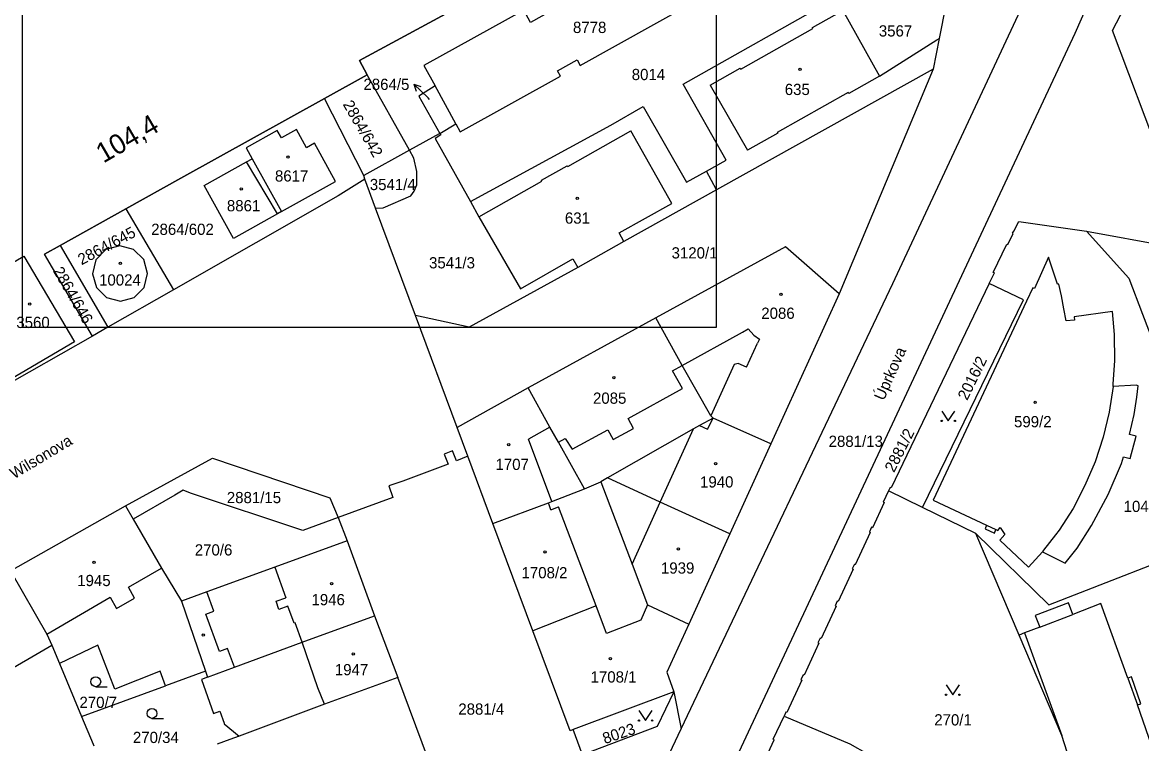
# Model space of a CAD drawing. Extents: x -564952 to -564307, y -1202373 to -1201847.
# Drawn here: x -564645.4 to -564475.9, y -1202200.5 to -1202091.3 of the extents above; entities that cross this region are included whole.
import ezdxf

# ---------------------------------------------------------------- set-up
doc = ezdxf.new("R2010")
doc.units = 0
for name, color, linetype in [('Hranice parcel', 7, 'Continuous'), ('Parcelní čísla', 7, 'Continuous'), ('Pop  PČ popisy', 7, 'Continuous'), ('Vnitřní kresba', 7, 'Continuous'), ('Vrstva 63', 7, 'Continuous'), ('Vrstva 7', 7, 'Continuous'), ('Značky budov', 7, 'Continuous'), ('Značky kultur', 7, 'Continuous')]:
    doc.layers.add(name, color=color, linetype=linetype)

msp = doc.modelspace()

# ---------------------------------------------------------------- linework, layer by layer
at = {"layer": 'Hranice parcel'}
for p, q in [((-564545.32, -1202100.65), (-564521.82, -1202087.35)), ((-564506.54, -1202093.7), (-564507.46, -1202098.37)), ((-564584.58, -1202097.8), (-564582.88, -1202100.89)), ((-564507.46, -1202098.37), (-564540.26, -1202116.64)), ((-564507.46, -1202098.37), (-564521.72, -1202132.36)), ((-564599.65, -1202102.83), (-564593.15, -1202099.21)), ((-564586.77, -1202110.65), (-564593.15, -1202099.21)), ((-564579.72, -1202106.62), (-564582.88, -1202100.89)), ((-564593.69, -1202114.49), (-564599.65, -1202102.83)), ((-564582.16, -1202108.09), (-564579.72, -1202106.62)), ((-564577.51, -1202118.41), (-564556.26, -1202106.85)), ((-564610.56, -1202111.95), (-564606.12, -1202119.94)), ((-564586.77, -1202110.65), (-564593.69, -1202114.49)), ((-564540.26, -1202116.64), (-564541.8, -1202113.81)), ((-564593.53, -1202115), (-564593.69, -1202114.49)), ((-564591.89, -1202119.4), (-564593.53, -1202115)), ((-564577.51, -1202118.41), (-564576.24, -1202120.72)), ((-564639.63, -1202125.04), (-564629.71, -1202119.53)), ((-564629.71, -1202119.53), (-564622.49, -1202131.77)), ((-564585.83, -1202135.64), (-564591.89, -1202119.4)), ((-564484.26, -1202122.87), (-564466.68, -1202126.15)), ((-564642, -1202126.36), (-564639.63, -1202125.04)), ((-564639.63, -1202125.04), (-564632.41, -1202137.43)), ((-564634.78, -1202138.78), (-564642, -1202126.36)), ((-564545.63, -1202198.24), (-564513.56, -1202130.84)), ((-564622.49, -1202131.77), (-564632.41, -1202137.43)), ((-564521.72, -1202132.36), (-564532.03, -1202155.1)), ((-564579.54, -1202152.6), (-564585.83, -1202135.64)), ((-564632.41, -1202137.43), (-564634.78, -1202138.78)), ((-564549.46, -1202136.04), (-564568.78, -1202146.64)), ((-564634.78, -1202138.78), (-564652.84, -1202149.09)), ((-564568.78, -1202146.64), (-564579.54, -1202152.6)), ((-564532.03, -1202155.1), (-564540.8, -1202151.2)), ((-564577.92, -1202156.95), (-564579.54, -1202152.6)), ((-564532.03, -1202155.1), (-564538.25, -1202168.75)), ((-564574.13, -1202167.15), (-564577.92, -1202156.95)), ((-564560.27, -1202161.89), (-564557.78, -1202160.84)), ((-564556.78, -1202160.27), (-564557.78, -1202160.84)), ((-564513.99, -1202161.71), (-564514.25, -1202162.22)), ((-564509.08, -1202164.74), (-564514.25, -1202162.22)), ((-564647.18, -1202174.34), (-564629.78, -1202164.5)), ((-564629.78, -1202164.5), (-564628.62, -1202166.49)), ((-564500.99, -1202168.69), (-564509.08, -1202164.74)), ((-564597.56, -1202166.27), (-564596.22, -1202169.81)), ((-564568.07, -1202183.42), (-564574.13, -1202167.15)), ((-564596.22, -1202169.81), (-564607.17, -1202173.79)), ((-564596.22, -1202169.81), (-564592.04, -1202181.12)), ((-564538.25, -1202168.75), (-564544.47, -1202182.4)), ((-564494.46, -1202184.06), (-564500.99, -1202168.69)), ((-564621.26, -1202178.92), (-564617.66, -1202189.51)), ((-564550.71, -1202179.48), (-564544.47, -1202182.4)), ((-564602.99, -1202185.12), (-564592.04, -1202181.12)), ((-564592.04, -1202181.12), (-564588.53, -1202190.48)), ((-564488, -1202199.27), (-564494.46, -1202184.06)), ((-564633.95, -1202185.59), (-564639.75, -1202188.35)), ((-564639.75, -1202188.35), (-564636.4, -1202196.4)), ((-564617.66, -1202189.51), (-564623.69, -1202191.73)), ((-564617.66, -1202189.51), (-564617.35, -1202190.41)), ((-564636.4, -1202196.4), (-564623.69, -1202191.73)), ((-564546.74, -1202192.63), (-564562, -1202198.37)), ((-564546.74, -1202192.63), (-564545.63, -1202198.24)), ((-564547.82, -1202202.85), (-564545.63, -1202198.24)), ((-564481.73, -1202218.41), (-564488, -1202199.27))]:
    msp.add_line(p, q, dxfattribs=at)
for points in [[(-564490.61, -1202037.43), (-564485.84, -1202045.71), (-564483.2, -1202051.32), (-564481.59, -1202056.49), (-564480.56, -1202063.21), (-564480.33, -1202068.72), (-564480.73, -1202075.46), (-564482.21, -1202082.88), (-564484.11, -1202088.61), (-564486.01, -1202092.94), (-564492.26, -1202106.34), (-564537.63, -1202203.39), (-564539.05, -1202206.7), (-564540.49, -1202210.49), (-564542.11, -1202215.98)], [(-564501.71, -1202041.71), (-564510.03, -1202046.63), (-564524.57, -1202055.16), (-564524.06, -1202056.17), (-564524.06, -1202056.17), (-564558.26, -1202076.16), (-564568.86, -1202083.22), (-564594.31, -1202097.06), (-564593.15, -1202099.21), (-564599.65, -1202102.83), (-564621.36, -1202114.89), (-564629.71, -1202119.53), (-564639.63, -1202125.04), (-564642, -1202126.36)], [(-564513.56, -1202130.84), (-564493.88, -1202088.69), (-564491.84, -1202083.54), (-564490.32, -1202078.4), (-564489.39, -1202070.74), (-564489.54, -1202063.63), (-564490.98, -1202056.1), (-564493.78, -1202048.14), (-564495.85, -1202043.53)], [(-564593.15, -1202099.21), (-564594.31, -1202097.06), (-564568.86, -1202083.22), (-564558.26, -1202076.16)], [(-564503.26, -1202076.98), (-564506.29, -1202092.45), (-564506.54, -1202093.7)], [(-564471.12, -1202112.99), (-564472.91, -1202112.19), (-564480.33, -1202092.49), (-564473.1, -1202078.61)], [(-564579.72, -1202106.62), (-564579.07, -1202107.87), (-564563.9, -1202099.44), (-564564.37, -1202098.6), (-564561.39, -1202096.95), (-564560.92, -1202097.79), (-564538.6, -1202085.32), (-564537.9, -1202086.54), (-564536.02, -1202085.5), (-564536.68, -1202084.26), (-564534.85, -1202083.23)], [(-564566.49, -1202087.78), (-564565.45, -1202089.65), (-564568.43, -1202091.3), (-564569.47, -1202089.44), (-564584.58, -1202097.8)], [(-564520.73, -1202089.2), (-564521.15, -1202089.48), (-564515.62, -1202099.42)], [(-564515.62, -1202099.42), (-564506.92, -1202093.94), (-564506.54, -1202093.7)], [(-564582.88, -1202100.89), (-564585.37, -1202102.47), (-564582.16, -1202108.09)], [(-564541.8, -1202113.81), (-564538.8, -1202112.13), (-564545.32, -1202100.65)], [(-564629.71, -1202119.53), (-564621.36, -1202114.89), (-564599.65, -1202102.83)], [(-564556.26, -1202106.85), (-564551.4, -1202104.02), (-564544.83, -1202115.5), (-564541.8, -1202113.81)], [(-564606.12, -1202119.94), (-564597.95, -1202115.39), (-564601.16, -1202109.59), (-564602.38, -1202110.27), (-564603.88, -1202107.5), (-564606.16, -1202108.76), (-564606.78, -1202107.65), (-564611.49, -1202110.28), (-564610.56, -1202111.95)], [(-564582.16, -1202108.09), (-564582.25, -1202108.14), (-564586.77, -1202110.65)], [(-564582.16, -1202108.09), (-564582.03, -1202108.32), (-564582.87, -1202108.86), (-564577.51, -1202118.41)], [(-564606.12, -1202119.94), (-564606.73, -1202120.28), (-564613.43, -1202124), (-564617.83, -1202116), (-564611.43, -1202112.4), (-564610.56, -1202111.95)], [(-564591.89, -1202119.4), (-564590.74, -1202119.38), (-564586.58, -1202117.56), (-564586.07, -1202116.85), (-564585.67, -1202115.88), (-564585.64, -1202113.86), (-564586.1, -1202111.83), (-564586.77, -1202110.65)], [(-564593.53, -1202115), (-564597.56, -1202117.54), (-564622.49, -1202131.77)], [(-564540.26, -1202116.64), (-564554.31, -1202124.46), (-564561.29, -1202128.42)], [(-564576.24, -1202120.72), (-564569.95, -1202131.64), (-564562.02, -1202127.1), (-564561.29, -1202128.42)], [(-564495.28, -1202122.88), (-564494.48, -1202121.45), (-564484.26, -1202122.87)], [(-564498.98, -1202130.82), (-564498.2, -1202129.22), (-564498.38, -1202129.13), (-564496.32, -1202124.84), (-564496.15, -1202124.92), (-564495.36, -1202123.27), (-564495.45, -1202123.22), (-564495.28, -1202122.88)], [(-564484.26, -1202122.87), (-564477.85, -1202129.99), (-564475.76, -1202135.44), (-564470.96, -1202147.96)], [(-564634.23, -1202127.23), (-564634.77, -1202129.33), (-564634.17, -1202131.42), (-564632.66, -1202132.95), (-564630.54, -1202133.5), (-564628.45, -1202132.93), (-564626.94, -1202131.4), (-564626.41, -1202129.29), (-564626.99, -1202127.19), (-564628.53, -1202125.67), (-564630.63, -1202125.11), (-564632.72, -1202125.68), (-564634.23, -1202127.23)], [(-564521.72, -1202132.36), (-564529.81, -1202125.26), (-564549.46, -1202136.04)], [(-564649.66, -1202146.78), (-564652.32, -1202142.22), (-564654.66, -1202138.21), (-564657.3, -1202133.69), (-564645.16, -1202126.66), (-564637.48, -1202139.67), (-564649.66, -1202146.78)], [(-564483.51, -1202167.45), (-564480.96, -1202162.75), (-564478.98, -1202158.08), (-564478.64, -1202157.07), (-564477.65, -1202157.31), (-564476.75, -1202153.95), (-564477.75, -1202153.68), (-564477.04, -1202150.63), (-564476.65, -1202148.03), (-564476.45, -1202146.29), (-564476.74, -1202146.23), (-564480.24, -1202146.43), (-564480.21, -1202145.99), (-564479.97, -1202142.53), (-564480.01, -1202138.56), (-564480.32, -1202135.08), (-564486.13, -1202135.85), (-564486.06, -1202136.35), (-564487.36, -1202136.45), (-564487.67, -1202134.63), (-564488.03, -1202132.71), (-564488.44, -1202130.91), (-564488.66, -1202130.93), (-564489.99, -1202126.85), (-564492.12, -1202131.58), (-564492.39, -1202131.47), (-564493.34, -1202133.51), (-564507.46, -1202163.65), (-564499.39, -1202167.41), (-564499.61, -1202167.95), (-564498.2, -1202168.6), (-564497.98, -1202168.07), (-564497.67, -1202168.21), (-564497.31, -1202167.78), (-564496.62, -1202168.83), (-564497.38, -1202169.7), (-564493.03, -1202173.79), (-564490.94, -1202171.44), (-564487.48, -1202173.17), (-564485.69, -1202170.87), (-564483.51, -1202167.45)], [(-564561.29, -1202128.42), (-564577.72, -1202137.44), (-564585.83, -1202135.64)], [(-564498.98, -1202130.82), (-564513.85, -1202161.77), (-564513.99, -1202161.71)], [(-564509.08, -1202164.74), (-564493.77, -1202133.3), (-564498.98, -1202130.82)], [(-564540.8, -1202151.2), (-564541.14, -1202150.85), (-564545.46, -1202143.23), (-564549.46, -1202136.04)], [(-564560.27, -1202161.89), (-564564.19, -1202154.86), (-564565.51, -1202152.55), (-564568.78, -1202146.64)], [(-564540.8, -1202151.2), (-564542.86, -1202152.33), (-564543.76, -1202152.82), (-564556.78, -1202160.27)], [(-564577.92, -1202156.95), (-564579.66, -1202157.65), (-564580.24, -1202156.18), (-564581.49, -1202156.65), (-564580.9, -1202158.2), (-564587.76, -1202160.75), (-564589.91, -1202161.48), (-564589.27, -1202163.23), (-564597.56, -1202166.27)], [(-564629.78, -1202164.5), (-564616.6, -1202157.29), (-564598.81, -1202163.26), (-564597.56, -1202166.27)], [(-564557.78, -1202160.84), (-564553.06, -1202173.32), (-564550.71, -1202179.48)], [(-564538.25, -1202168.75), (-564548.8, -1202163.92), (-564556.78, -1202160.27)], [(-564597.56, -1202166.27), (-564602.89, -1202168.22), (-564619.91, -1202162.56), (-564621.02, -1202162.13), (-564622.28, -1202162.87), (-564628.62, -1202166.49)], [(-564574.13, -1202167.15), (-564565.71, -1202164.02), (-564565.23, -1202163.83), (-564560.27, -1202161.89)], [(-564514.25, -1202162.22), (-564515.03, -1202163.91), (-564514.9, -1202163.97), (-564516.67, -1202167.81), (-564516.81, -1202167.74)], [(-564628.62, -1202166.49), (-564624.3, -1202173.94), (-564621.26, -1202178.92)], [(-564516.81, -1202167.74), (-564517.13, -1202168.44), (-564517, -1202168.51), (-564519.26, -1202173.4), (-564519.4, -1202173.33), (-564519.73, -1202174.04), (-564519.59, -1202174.1), (-564521.85, -1202178.98), (-564521.99, -1202178.92), (-564522.32, -1202179.64), (-564522.18, -1202179.7), (-564524.44, -1202184.58), (-564524.58, -1202184.52), (-564524.91, -1202185.23)], [(-564500.99, -1202168.69), (-564489.98, -1202179.46), (-564465.07, -1202169.78)], [(-564647.18, -1202174.34), (-564641.67, -1202183.91), (-564640.9, -1202185.58), (-564639.75, -1202188.35)], [(-564607.17, -1202173.79), (-564617.45, -1202177.53), (-564621.26, -1202178.92)], [(-564556.93, -1202183.82), (-564558.51, -1202179.64), (-564568.07, -1202183.42)], [(-564550.71, -1202179.48), (-564551.74, -1202181.8), (-564556.93, -1202183.82)], [(-564458.87, -1202196.74), (-564473.97, -1202202.06), (-564476.51, -1202194.63), (-564476.01, -1202194.45), (-564477.42, -1202190.36), (-564477.98, -1202190.57), (-564482.07, -1202179.28), (-564486.31, -1202180.92), (-564486.99, -1202179.15), (-564492.02, -1202181.09), (-564491.34, -1202182.86), (-564493.63, -1202183.74), (-564494.46, -1202184.06)], [(-564544.47, -1202182.4), (-564547.79, -1202189.69), (-564546.74, -1202192.63)], [(-564562, -1202198.37), (-564562.44, -1202198.54), (-564568.07, -1202183.42)], [(-564623.69, -1202191.73), (-564624.53, -1202189.5), (-564631.36, -1202192.25), (-564633.95, -1202185.59)], [(-564617.35, -1202190.41), (-564613.26, -1202188.9), (-564602.99, -1202185.12)], [(-564524.91, -1202185.23), (-564524.77, -1202185.29), (-564527.02, -1202190.14)], [(-564527.02, -1202190.14), (-564527.16, -1202190.08), (-564527.51, -1202190.83), (-564527.37, -1202190.89), (-564529.64, -1202195.79), (-564529.77, -1202195.73), (-564530.05, -1202196.32)], [(-564617.35, -1202190.41), (-564618.26, -1202190.8), (-564616.42, -1202195.93), (-564615.48, -1202195.6), (-564614.84, -1202197.38), (-564614.8, -1202197.48), (-564612.57, -1202199.34)], [(-564588.53, -1202190.48), (-564599.64, -1202194.53), (-564612.57, -1202199.34)], [(-564573.02, -1202232.4), (-564578.7, -1202216.81), (-564583.08, -1202205.12), (-564588.53, -1202190.48)], [(-564546.74, -1202192.63), (-564549.25, -1202197.89), (-564560.56, -1202202.2), (-564562, -1202198.37)], [(-564636.4, -1202196.4), (-564634.68, -1202200.55), (-564634.56, -1202200.83)], [(-564531.54, -1202199.9), (-564531.68, -1202199.84), (-564530.05, -1202196.32)], [(-564530.05, -1202196.32), (-564520.07, -1202200.53), (-564517.42, -1202202.04), (-564516.45, -1202203.06), (-564515.15, -1202205.05), (-564512.46, -1202207.51), (-564511.71, -1202209.04), (-564510.44, -1202211.22), (-564507.27, -1202214.23), (-564507.22, -1202214.4), (-564507.04, -1202214.34), (-564506.39, -1202216.27), (-564506.24, -1202216.69), (-564503.5, -1202224.55), (-564503.06, -1202225.8)], [(-564612.57, -1202199.34), (-564613.95, -1202199.85), (-564615.87, -1202200.58)], [(-564534.37, -1202205.65), (-564534.23, -1202205.71), (-564531.54, -1202199.9)]]:
    msp.add_lwpolyline(points, dxfattribs=at)
at = {"layer": 'Pop  PČ popisy'}
for p, q in [((-564583.95, -1202102.73), (-564586.11, -1202100.65)), ((-564586.11, -1202100.65), (-564585.04, -1202100.98)), ((-564586.11, -1202100.65), (-564585.74, -1202101.7)), ((-564583.72, -1202102.95), (-564583.95, -1202102.73))]:
    msp.add_line(p, q, dxfattribs=at)
at = {"layer": 'Vnitřní kresba'}
for p, q in [((-564525.76, -1202092.07), (-564521.15, -1202089.48)), ((-564536.61, -1202098.36), (-564525.68, -1202092.21)), ((-564525.68, -1202092.21), (-564525.76, -1202092.07)), ((-564541.22, -1202100.77), (-564536.69, -1202098.22)), ((-564536.69, -1202098.22), (-564536.61, -1202098.36)), ((-564515.62, -1202099.42), (-564520.26, -1202102.03)), ((-564541.22, -1202100.77), (-564535.57, -1202110.64)), ((-564520.34, -1202101.89), (-564531.07, -1202107.93)), ((-564520.26, -1202102.03), (-564520.34, -1202101.89)), ((-564562.81, -1202113.12), (-564553.23, -1202107.7)), ((-564547.06, -1202118.68), (-564553.23, -1202107.7)), ((-564530.99, -1202108.06), (-564535.57, -1202110.64)), ((-564531.07, -1202107.93), (-564530.99, -1202108.06)), ((-564606.73, -1202120.28), (-564611.43, -1202112.4)), ((-564566.79, -1202115.19), (-564562.89, -1202112.98)), ((-564562.89, -1202112.98), (-564562.81, -1202113.12)), ((-564576.24, -1202120.72), (-564566.72, -1202115.33)), ((-564566.72, -1202115.33), (-564566.79, -1202115.19)), ((-564555.03, -1202123.14), (-564547.06, -1202118.68)), ((-564554.31, -1202124.46), (-564555.03, -1202123.14)), ((-564545.46, -1202143.23), (-564536.36, -1202138.2)), ((-564536.36, -1202138.2), (-564535.46, -1202137.7)), ((-564535.46, -1202137.7), (-564534.65, -1202138.66)), ((-564534.65, -1202138.66), (-564533.78, -1202139.23)), ((-564533.78, -1202139.23), (-564534.07, -1202139.86)), ((-564535.72, -1202143.49), (-564534.07, -1202139.86)), ((-564546.94, -1202144.04), (-564545.46, -1202143.23)), ((-564545.45, -1202146.73), (-564546.94, -1202144.04)), ((-564537.62, -1202143.09), (-564541.14, -1202150.85)), ((-564537.02, -1202142.91), (-564537.62, -1202143.09)), ((-564535.72, -1202143.49), (-564537.02, -1202142.91)), ((-564553.65, -1202151.27), (-564545.45, -1202146.73)), ((-564480.24, -1202146.43), (-564480.83, -1202150.3)), ((-564541.64, -1202152.88), (-564540.8, -1202151.2)), ((-564480.83, -1202150.3), (-564481.74, -1202154.11)), ((-564565.51, -1202152.55), (-564568.72, -1202154.4)), ((-564555.93, -1202154.46), (-564552.84, -1202152.77)), ((-564552.84, -1202152.77), (-564553.65, -1202151.27)), ((-564548.8, -1202163.92), (-564543.76, -1202152.82)), ((-564542.86, -1202152.33), (-564541.64, -1202152.88)), ((-564565.23, -1202163.83), (-564568.72, -1202154.4)), ((-564564.19, -1202154.86), (-564563.17, -1202154.29)), ((-564563.17, -1202154.29), (-564562.13, -1202155.89)), ((-564562.13, -1202155.89), (-564556.75, -1202152.96)), ((-564556.75, -1202152.96), (-564555.93, -1202154.46)), ((-564481.74, -1202154.11), (-564482.96, -1202157.83)), ((-564482.96, -1202157.83), (-564484.49, -1202161.42)), ((-564484.49, -1202161.42), (-564486.29, -1202164.9)), ((-564565.35, -1202165.08), (-564565.71, -1202164.02)), ((-564565.35, -1202165.08), (-564564.19, -1202164.63)), ((-564558.51, -1202179.64), (-564564.19, -1202164.63)), ((-564553.06, -1202173.32), (-564548.8, -1202163.92)), ((-564486.29, -1202164.9), (-564488.41, -1202168.17)), ((-564499.39, -1202167.41), (-564497.98, -1202168.07)), ((-564488.95, -1202168.87), (-564490.77, -1202171.21)), ((-564488.41, -1202168.17), (-564488.95, -1202168.87)), ((-564490.77, -1202171.21), (-564490.94, -1202171.44)), ((-564629.29, -1202176.8), (-564624.3, -1202173.94)), ((-564607.17, -1202173.79), (-564605.49, -1202178.4)), ((-564628.38, -1202178.46), (-564629.29, -1202176.8)), ((-564616.37, -1202180.46), (-564617.45, -1202177.53)), ((-564641.67, -1202183.91), (-564632.06, -1202178.33)), ((-564632.06, -1202178.33), (-564631.12, -1202180.03)), ((-564631.12, -1202180.03), (-564628.38, -1202178.46)), ((-564606.94, -1202178.93), (-564605.49, -1202178.4)), ((-564606.52, -1202180.16), (-564606.94, -1202178.93)), ((-564605.17, -1202179.66), (-564606.52, -1202180.16)), ((-564604.21, -1202182.26), (-564605.17, -1202179.66)), ((-564617.59, -1202180.91), (-564616.37, -1202180.46)), ((-564615.52, -1202186.54), (-564617.59, -1202180.91)), ((-564491.34, -1202182.86), (-564486.31, -1202180.92)), ((-564604.09, -1202182.21), (-564604.21, -1202182.26)), ((-564602.99, -1202185.12), (-564604.09, -1202182.21)), ((-564493.63, -1202183.74), (-564488, -1202199.27)), ((-564654.37, -1202193.36), (-564640.9, -1202185.58)), ((-564614.3, -1202186.09), (-564615.52, -1202186.54)), ((-564613.26, -1202188.9), (-564614.3, -1202186.09)), ((-564600.63, -1202192.06), (-564602.99, -1202185.12)), ((-564477.98, -1202190.57), (-564476.51, -1202194.63)), ((-564599.64, -1202194.53), (-564600.63, -1202192.06))]:
    msp.add_line(p, q, dxfattribs=at)
at = {"layer": 'Vrstva 63'}
msp.add_lwpolyline([(-564540.34, -1202137.49), (-564645.34, -1202137.49), (-564645.34, -1201988.99), (-564540.34, -1201988.99)], close=True, dxfattribs=at)
at = {"layer": 'Značky budov'}
for centre in [(-564527.63, -1202098.38), (-564605.16, -1202111.68), (-564612.24, -1202116.5), (-564561.35, -1202117.93), (-564630.54, -1202127.76), (-564530.52, -1202132.47), (-564644.26, -1202133.93), (-564555.82, -1202145.1), (-564492.03, -1202148.83), (-564571.74, -1202155.23), (-564540.41, -1202158.09), (-564566.23, -1202171.46), (-564546.04, -1202171), (-564634.51, -1202173.04), (-564598.55, -1202176.29), (-564617.98, -1202184.06), (-564595.28, -1202186.92), (-564556.35, -1202187.63)]:
    msp.add_circle(centre, 0.175, dxfattribs=at)
at = {"layer": 'Značky kultur'}
for p, q in [((-564634.27, -1202191.87), (-564632.52, -1202191.87)), ((-564625.75, -1202196.67), (-564624, -1202196.67))]:
    msp.add_line(p, q, dxfattribs=at)
for points in [[(-564506.18, -1202150.13), (-564505.18, -1202151.63), (-564504.18, -1202150.13)], [(-564505.51, -1202191.59), (-564504.51, -1202193.09), (-564503.51, -1202191.59)], [(-564552.02, -1202195.5), (-564551.02, -1202197), (-564550.02, -1202195.5)]]:
    msp.add_lwpolyline(points, dxfattribs=at)
for centre, radius in [((-564506.18, -1202151.63), 0.1), ((-564504.18, -1202151.63), 0.1), ((-564634.27, -1202191.12), 0.75), ((-564505.51, -1202193.09), 0.1), ((-564503.51, -1202193.09), 0.1), ((-564625.75, -1202195.92), 0.75), ((-564552.02, -1202197), 0.1), ((-564550.02, -1202197), 0.1)]:
    msp.add_circle(centre, radius, dxfattribs=at)

# ---------------------------------------------------------------- texts
at = {"layer": 'Parcelní čísla'}
for s, p in [('8778', (-564562.01, -1202092.89)), ('3567', (-564515.7, -1202093.42)), ('8014', (-564553.11, -1202100.02)), ('2864/5', (-564593.73, -1202101.51)), ('635', (-564529.94, -1202102.28)), ('8617', (-564607.13, -1202115.38)), ('3541/4', (-564592.77, -1202116.68)), ('8861', (-564614.41, -1202119.89)), ('631', (-564563.23, -1202121.76)), ('2864/602', (-564625.87, -1202123.46)), ('3120/1', (-564547.08, -1202127.03)), ('3541/3', (-564583.8, -1202128.53)), ('10024', (-564633.76, -1202131.13)), ('3560', (-564646.29, -1202137.56)), ('2086', (-564533.5, -1202136.17)), ('2085', (-564558.98, -1202149.03)), ('599/2', (-564495.23, -1202152.59)), ('2881/13', (-564523.3, -1202155.56)), ('1707', (-564573.74, -1202159.06)), ('1940', (-564542.77, -1202161.71)), ('2881/15', (-564614.42, -1202164.08)), ('10495', (-564478.64, -1202165.42)), ('270/6', (-564619.27, -1202172.01)), ('1939', (-564548.69, -1202174.75)), ('1945', (-564637.07, -1202176.64)), ('1708/2', (-564569.8, -1202175.46)), ('1946', (-564601.6, -1202179.54)), ('1947', (-564598.06, -1202190.14)), ('1708/1', (-564559.34, -1202191.24)), ('270/7', (-564636.73, -1202195.09)), ('2881/4', (-564579.37, -1202196.11)), ('270/1', (-564507.31, -1202197.74)), ('270/34', (-564628.64, -1202200.4))]:
    msp.add_text(s, height=1.7, dxfattribs=at).set_placement(p)
for s, rotation, p in [('2864/642', 300, (-564596.91, -1202103.68)), ('2864/645', 28, (-564636.41, -1202128.07)), ('2864/646', 300, (-564640.8, -1202128.89)), ('2016/2', 64, (-564502.32, -1202148.63)), ('2881/2', 63, (-564513.4, -1202159.54)), ('8023', 19, (-564557.18, -1202200.58))]:
    msp.add_text(s, height=1.7, rotation=rotation, dxfattribs=at).set_placement(p)
at = {"layer": 'Pop  PČ popisy'}
for s, rotation, p in [('Úprkova', 66, (-564514.95, -1202148.66)), ('Wilsonova', 31, (-564646.62, -1202160.48))]:
    msp.add_text(s, height=1.7, rotation=rotation, dxfattribs=at).set_placement(p)
at = {"layer": 'Vrstva 7'}
msp.add_text('104,4', height=3, rotation=30.1377, dxfattribs=at).set_placement((-564633.11, -1202112.67))

doc.saveas('drawing.dxf')
